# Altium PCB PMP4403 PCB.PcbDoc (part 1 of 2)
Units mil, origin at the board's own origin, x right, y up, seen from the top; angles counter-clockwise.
Board outline 2204 x 1635 mil, 2 copper layers (Top Layer, Bottom Layer), stack 62 mil thick; 78 components, 89 nets, 246 pads, 22 vias.
Unrouted connection lines stored in the file: 1.
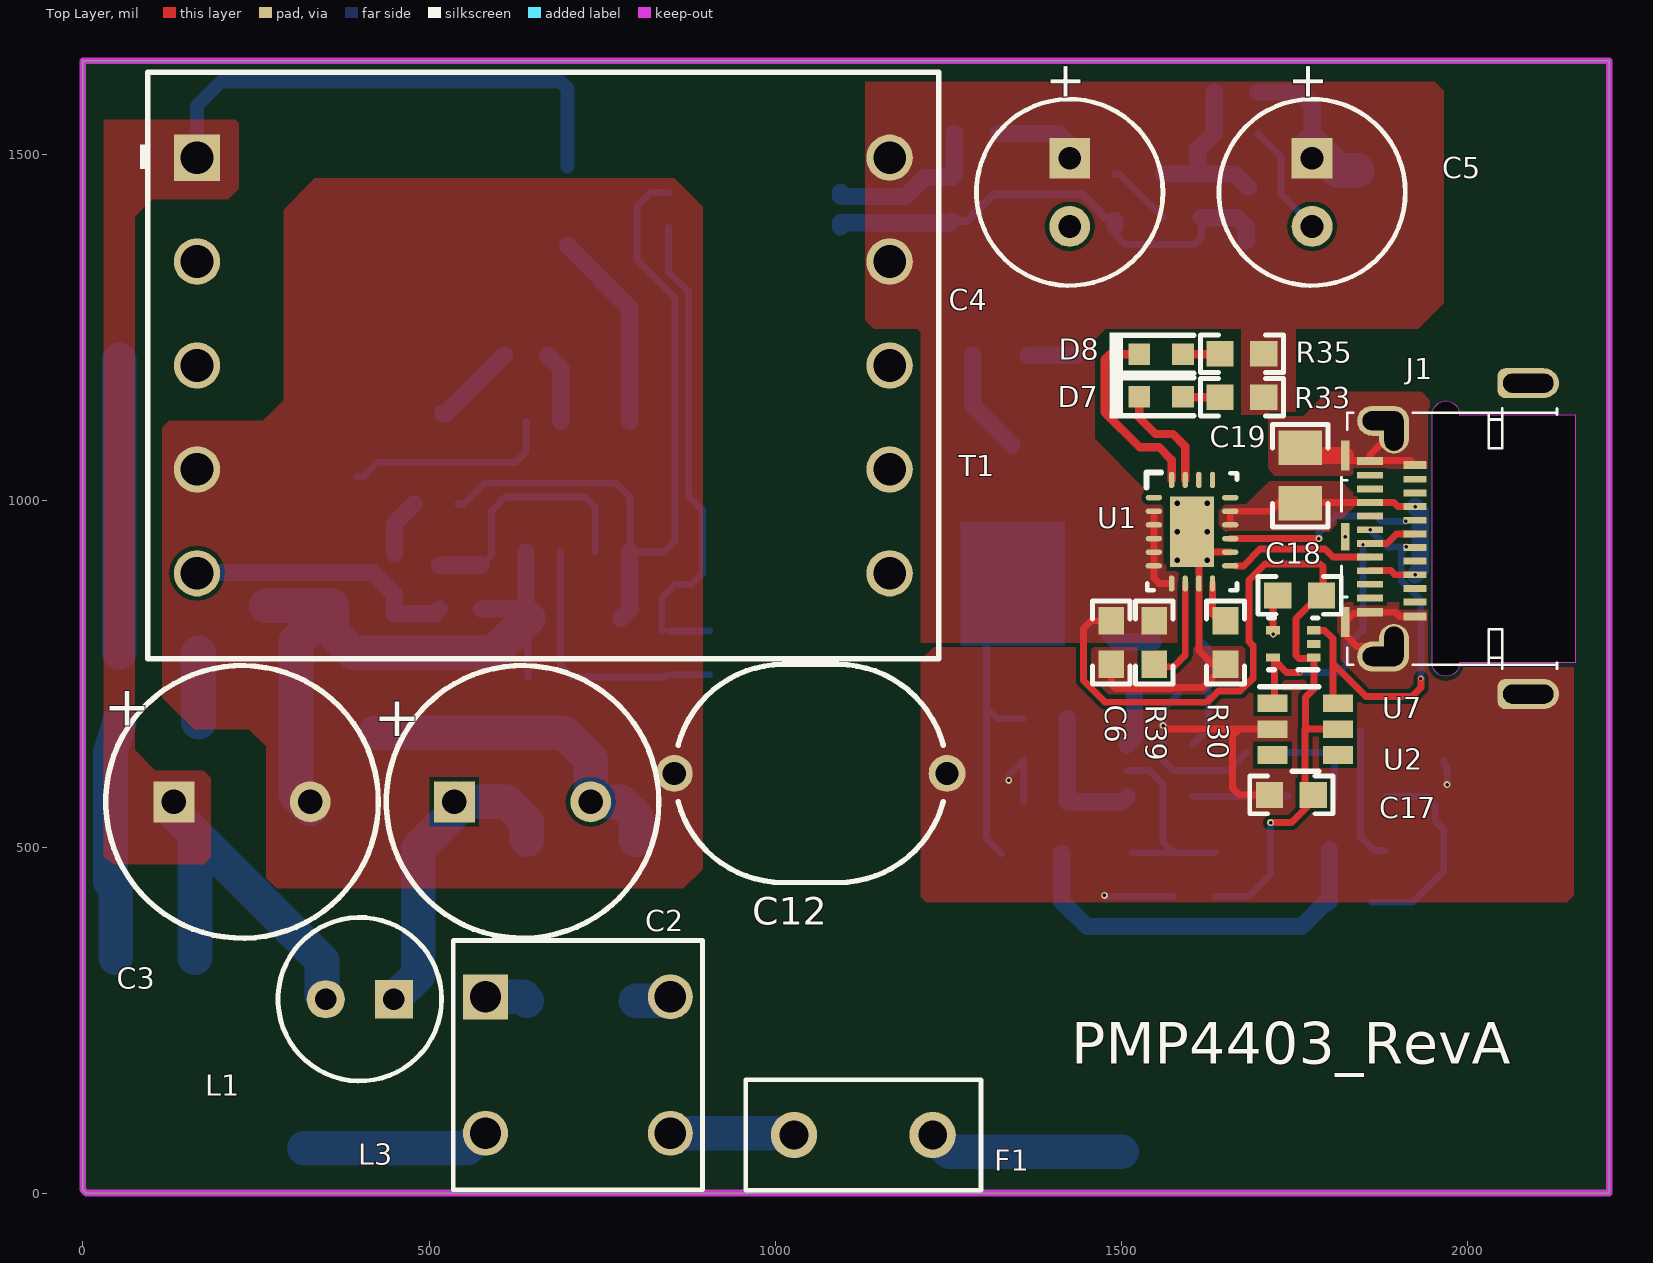
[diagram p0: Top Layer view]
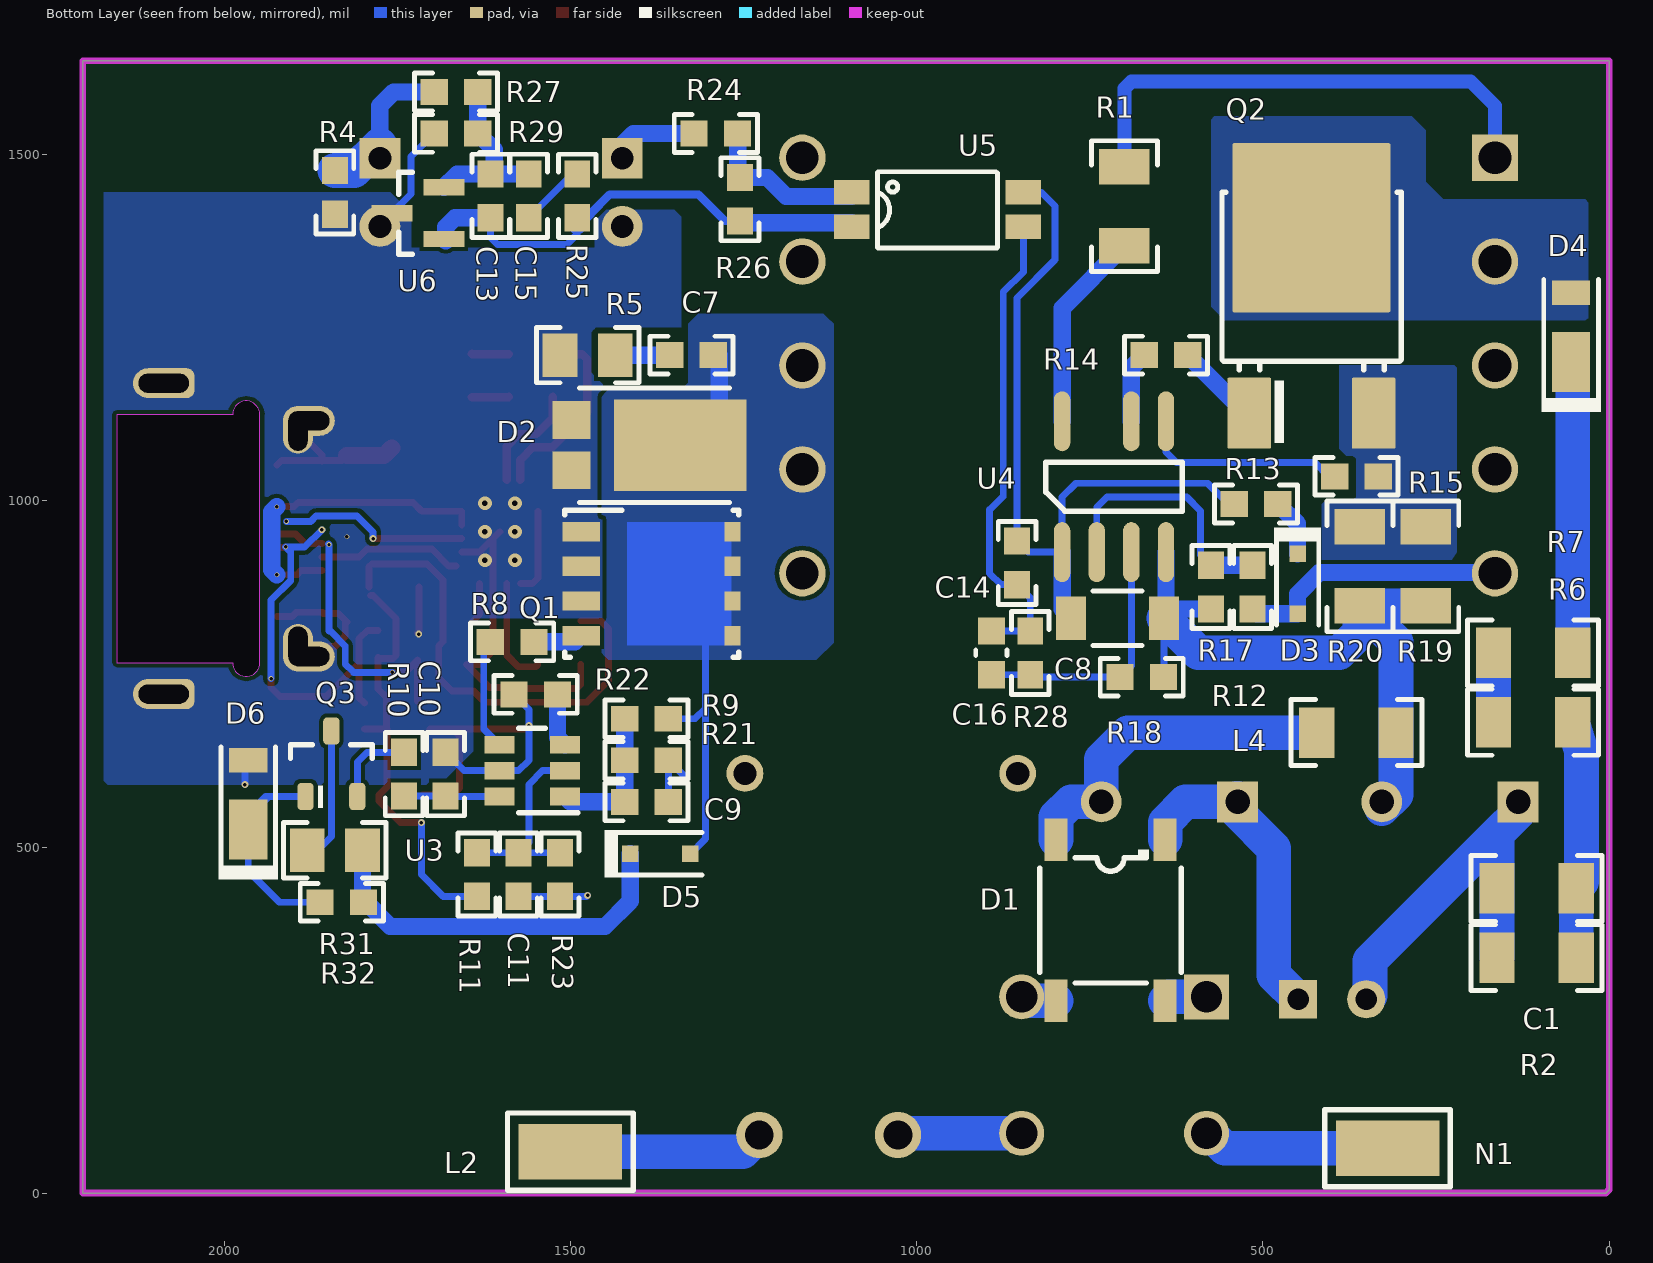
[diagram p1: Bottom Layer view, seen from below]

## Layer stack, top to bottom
Top Solder: solder mask 0.4, Solder Resist, Dk 3.5
Top Layer: signal copper 1.4
Dielectric1: core 59.2, FR-4, Dk 4.8
Bottom Layer: signal copper 1.4
Bottom Solder: solder mask 0.4, Solder Resist, Dk 3.5

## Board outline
5.02,0.42 0.02,5.42 0.02,1635.42 2204.02,1635.42 2204.02,0.42

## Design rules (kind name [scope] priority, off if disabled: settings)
AcuteAngle [All] p1: minimum=4.50000000000000E+0001 checktracksonly=FALSE
AssemblyTestPointUsage [All] p1: valid=2
Clearance Clearance_BoardEdge_MountingHoles [OnCopper and InComponentClass('Mounting Holes') vs IsKeepOut] p1: gap=40
Clearance Clearance_BoardEdge_Poly [OnCopper and InPoly vs IsKeepOut] p2: gap=25
Clearance Clearance_BoardEdge [OnCopper and Not InComponentClass('Logo') and not InComponentClass('FiducialMark') and not InRegion(1000,500,4000,800) and Not IsKeepout vs IsKeepOut] p3: gap=5
Clearance Clearance_Poly [InPolygon] p4: gap=6
Clearance [All] p5: gap=6
ComponentClearance ComponentClearance_Logo [All] p1: gap=10 collisioncheckmode=3 verticalgap=10 showdistances=TRUE
ComponentClearance ComponentClearance_ScrewToNut [(HasFootprint('NY PMS 440 0025 PH')) vs (HasFootprint('Keystone_1902C'))] p2: gap=5 collisioncheckmode=3 verticalgap=10 showdistances=FALSE
ComponentClearance ComponentClearance_MountingHoles [InComponentClass('Mounting Holes')] p3: gap=10 collisioncheckmode=3 verticalgap=100000 showdistances=FALSE
ComponentClearance ComponentClearance_SmallPassives [HasFootprint('0201*') or HasFootprint('0402*') or HasFootprint('0508') or HasFootprint('0603*') or HasFootprint('0612') or HasFootprint('0805*') or HasFootprint('0815*') or HasFootprint('0830*') or HasFootprint('1206*') or HasFootprint('1210*') or HasFootprint('1808*') or HasFootprint('1812*') or HasFootprint('1825*') or HasFootprint('2010*') or HasFootprint('2220*') or HasFootprint('2225*') or HasFootprint('2512*') or HasFootprint('2728*') or HasFootprint('3518*') vs HasFootprint('0201*') or HasFootprint('0402*') or HasFootprint('0508') or HasFootprint('0603*') or HasFootprint('0612') or HasFootprint('0805*') or HasFootprint('0815*') or HasFootprint('0830*') or HasFootprint('1206*') or HasFootprint('1210*') or HasFootprint('1808*') or HasFootprint('1812*') or HasFootprint('1825*') or HasFootprint('2010*') or HasFootprint('2220*') or HasFootprint('2225*') or HasFootprint('2512*') or HasFootprint('2728*') or HasFootprint('3518*')] p4: gap=10 collisioncheckmode=3 verticalgap=10 showdistances=FALSE
ComponentClearance ComponentClearance_THtoSMT [IsThruComponent vs IsSMTComponent] p5: gap=10 collisioncheckmode=3 verticalgap=100000 showdistances=FALSE
ComponentClearance ComponentClearance_THtoTH [IsThruComponent vs IsThruComponent] p6: gap=10 collisioncheckmode=3 verticalgap=100000 showdistances=FALSE
ComponentClearance [All] p7: gap=10 collisioncheckmode=3 verticalgap=10 showdistances=FALSE
DiffPairsRouting [All] p1: maxlimit=100 minlimit=10 mostfreqgap=10 toplayer_minwidth=15 toplayer_maxwidth=15 toplayer_prefwidth=15 bottomlayer_minwidth=15 bottomlayer_maxwidth=15 bottomlayer_prefwidth=15 maxuncoupledlength=1000
FabricationTestPointUsage TestPointUsage [All] p1: valid=2 allowmultiple=FALSE
FabricationTestpoint Testpoint [All] p1: side=3 testpointundercomponent=TRUE minsize=40 maxsize=100 preferedsize=60 minholesize=0 maxholesize=40 preferedholesize=32 testpointgrid=1 allowsidetop=TRUE allowsidebottom=TRUE usegrid=TRUE gridtolerance=0.01
FanoutControl Fanout_LCC [IsLCC] p1: bgadir=Out bgaviamode=Centered fanoutstyle=Auto fanoutdirection=Alternating viagrid=1 // Fanout_LCC (Default Rule)
FanoutControl Fanout_BGA [IsBGA] p2: bgadir=Out bgaviamode=Centered fanoutstyle=Auto fanoutdirection=Alternating viagrid=1 // Fanout_BGA (Default Rule)
FanoutControl Fanout_Default [All] p4: bgadir=Out bgaviamode=Centered fanoutstyle=Auto fanoutdirection=Alternating viagrid=1 // Fanout_Default (Default Rule)
FanoutControl Fanout_Small [(CompPinCount < 5)] p5: bgadir=Out bgaviamode=Centered fanoutstyle=Auto fanoutdirection=OutThenIn viagrid=1 // Fanout_Small (Default Rule)
HoleSize [All] p1: absolutevalues=TRUE maxlimit=251 minlimit=6 maxpercent=80.000 minpercent=20.000
MinimumAnnularRing [All] p1: minimumring=3
MinimumSolderMaskSliver MinimumSolderMaskSliver_Logo [InComponentClass('Logo') vs InComponentClass('Logo')] p1: minsoldermaskwidth=0.7
MinimumSolderMaskSliver [All] p2: minsoldermaskwidth=0
PlaneConnect [All] p1: planeconnectstyle=Direct reliefexpansion=10 reliefentries=4 reliefconductorwidth=10 reliefairgap=10
PolygonConnect [All] p1: connectstyle=Direct reliefconductorwidth=10 reliefentries=4 polygonreliefangle="90 Angle" airgapwidth=10
RoutingCorners [All] p1: cornerstyle=45-Degree minsetback=10 maxsetback=100
RoutingVias [All] p1: holewidth=16 width=34 viastyle="Through Hole" minholewidth=8 minwidth=16 maxholewidth=40 maxwidth=65
SMDToCorner [All] p1: distance=0
SilkToSilkClearance [All] p1: silktosilkclearance=0
SilkToSolderMaskClearance SilkscreenOverComponentPads [IsPad] p1: minsilkscreentomaskgap=0 clearancetoexposedcopper=TRUE
SolderMaskExpansion [All] p1: expansion=3
UnpouredPolygon [All] p1: allowunpoured=FALSE
Width [All] p1: maxlimit=100 minlimit=6 preferedwidth=10 checkconnectedcopper=TRUE
14 further rules are at their usual default settings.

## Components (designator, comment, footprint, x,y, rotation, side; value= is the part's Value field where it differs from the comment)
C1 "GRM31A5C2J331JW01D" 1206 105.02,440.42 r180 bottom
C2 "EEUED2G100" CAPPR5-10X20 635.02,565.42 r0 top
C3 "EEUED2G100" CAPPR5-10X20 230.02,565.42 r0 top
C4 "6SEPC470MW" SEPC_C9 1425.02,1445.42 r270 top
C5 "6SEPC470MW" SEPC_C9 1775.02,1445.42 r270 top
C6 "C1608X7R1E104K" 0603 1485.02,795.42 r270 top
C7 "06035A102KAT2A" 0603 1325.02,1210.42 r180 bottom
C8 "GMK316AB7106KL-TR" 1206_190 710.02,830.42 r180 bottom
C9 "06035A150JAT2A" 0603 1390.02,565.42 r180 bottom
C10 "GRM188R61E105KA12D" 0603 1680.02,605.42 r90 bottom
C11 "06035A150JAT2A" 0603 1575.02,460.42 r270 bottom
C12 "DE1B3KX101K" CAPRD1000W60D1000H1400 1051.02,606.42 r180 top
C13 "C0603X223K5RACTU" 0603 1615.02,1440.42 r270 bottom
C14 "C0603X223K5RACTU" 0603 855.02,910.42 r270 bottom
C15 "C0603X223K5RACTU" 0603 1560.02,1440.42 r270 bottom
C16 "C0603C105K3RACTU" 0603_095 892.02,780.42 r270 bottom
C17 "06033C104JAT2A" 0603 1745.02,575.42 r180 top
C18 "06033C104JAT2A" 0603 1757.02,863.42 r180 top
C19 "C0805C106K8PACTU" 0805_HV 1758.02,1036.42 r90 top
D1 "MDB6S" MICRODIP_4 720.02,394.42 r270 bottom
D2 "PDS1040L-13" PowerDI5 1420.02,1080.42 r180 bottom
D3 "BAS20HT1" sod-323 450.02,880.42 r270 bottom
D4 "DFLR1600-7" powerDI123 55.02,1250.42 r90 bottom
D5 "BAS20HT1" sod-323 1370.02,490.42 r180 bottom
D6 "DFLZ6V2-7" powerDI123 1965.02,575.42 r90 bottom
D7 "150060GS75000" WL-SMCW_GREEN 1557.02,1150.42 r0 top
D8 "150060GS75000" WL-SMCW_GREEN 1557.02,1211.69 r0 top
F1 "39213150000" FUSE_392 1127.02,84.42 r0 top
J1 "20-0000016-01" Lintes_20-0000016-01 2155.02,945.42 r90 top
L1 "7447462471" WE-TI_5075 400.02,280.42 r180 top
L2 "TESTPOINT" Keystone_5019 1500.02,60.42 r180 bottom
L3 "RLTI-1081" IND_RLTI-1081 715.02,185.42 r0 top
L4 "HZ1206E152R-10" 1206 365.02,665.42 r180 bottom
N1 "TESTPOINT" Keystone_5019 320.02,65.42 r0 bottom
Q1 "CSD18509Q5B" TRANS_NexFET_Q5B 1375.02,880.42 r180 bottom
Q2 "AOD7N65" DPAK 430.02,1260.42 r90 bottom
Q3 "MMBT3904" SOT-23 1845.02,620.42 r90 bottom
R1 "CRCW1206100KJNEA" 1206 700.02,1425.42 r90 bottom
R2 "CRCW1206330KJNEA" 1206 105.02,340.42 r0 bottom
R4 "CRCW0603100KJNEA" 0603 1840.02,1445.42 r90 bottom
R5 "CRCW080520R0JNEA" 0805_HV 1475.02,1210.42 r0 bottom
R6 "CRCW1206150RJNEA" 1206 110.02,680.42 r180 bottom
R7 "CRCW1206150RJNEA" 1206 110.02,780.42 r0 bottom
R8 "CRCW06032R00JNEA" 0603 1584.02,796.42 r0 bottom
R9 "CRCW0603150KFKEA" 0603 1390.02,685.42 r180 bottom
R10 "CRCW06032R00JNEA" 0603 1740.02,605.42 r90 bottom
R11 "CRCW060391K0JNEA" 0603 1635.02,460.42 r270 bottom
R12 "CRCW060368K0JNEA" 0603 515.02,875.42 r270 bottom
R13 "CRCW060322R0JNEA" 0603 510.02,995.42 r180 bottom
R14 "CRCW06030000Z0EA" 0603 640.02,1210.42 r180 bottom
R15 "CRCW06031K50JNEA" 0603 365.02,1035.42 r180 bottom
R17 "CRCW060339K0JNEA" 0603 575.02,875.42 r90 bottom
R18 "CRCW060320K0FKEA" 0603 675.02,745.42 r0 bottom
R19 "CRCW12061R00JNEA" 1206 265.02,905.42 r90 bottom
R20 "CRCW12062R00JNEA" 1206 360.02,905.42 r90 bottom
R21 "CRCW060310K0JNEA" 0603 1390.02,625.42 r0 bottom
R22 "CRCW060313K0JNEA" 0603 1550.02,720.42 r180 bottom
R23 "CRCW060347K0JNEA" 0603 1514.95,460.42 r90 bottom
R24 "CRCW06031K00FKEA" 0603 1290.02,1530.42 r0 bottom
R25 "CRCW060322K0JNEA" 0603 1490.02,1440.42 r90 bottom
R26 "CRCW06032K00FKEA" 0603 1255.02,1435.42 r90 bottom
R27 "CRCW060310K0FKEA" 0603 1665.02,1590.42 r0 bottom
R28 "CRCW0603100KFKEA" 0603 836.02,780.42 r90 bottom
R29 "CRCW060310K0FKEA" 0603 1665.02,1530.42 r180 bottom
R30 "CRCW0603100KFKEA" 0603 1650.02,795.42 r90 top
R31 "CRCW080522R0JNEA" 0805_HV 1840.02,495.42 r180 bottom
R32 "CRCW06031K00FKEA" 0603 1830.02,420.42 r180 bottom
R33 "CRCW060310K0JNEA" 0603 1673.67,1149.63 r0 top
R35 "CRCW060310K0JNEA" 0603 1673.67,1212.42 r0 top
R39 "CRCW060310K0JNEA" 0603 1547.07,795.42 r90 top
T1 "750342752" Wurth_750342752 665.02,1195.42 r0 top
U1 "TPS25810RVC" RVC0020A 1601.67,955.42 r0 top
U2 "TPS2514ADBV" DBV0006A_N 1765.02,670.42 r0 top
U3 "UCC24632" DBV0006A_N 1555.02,610.42 r0 bottom
U4 "UCC28740DR" D0007A_N 715.02,1020.42 r90 bottom
U5 "TCMT1107" SOP-4 970.02,1420.42 r180 bottom
U6 "TL431AIDBZR" DBZ0003A_N 1720.02,1415.42 r0 bottom
U7 "TPD2E001DRLRG4" DRL0005A 1748.02,793.42 r180 top

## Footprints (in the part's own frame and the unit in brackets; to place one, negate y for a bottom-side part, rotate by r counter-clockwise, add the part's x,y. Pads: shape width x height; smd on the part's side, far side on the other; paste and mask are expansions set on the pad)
0603 [mm] "0603 from SM-752 data"
  rect 1x0.95 smd: 1(-0.8,0) 2(0.8,0)
  silkscreen extent -1.52,-0.69 1.52,0.69, body extent -0.87,-0.47 0.87,0.47, height 0.85
0603_095 [mm] "0603_095"
  rect 1x1 smd: 1(-0.8,0) 2(0.8,0)
  silkscreen extent -0.1,-0.58 0.1,0.58, body extent -0.87,-0.48 0.87,0.48, height 0.95
0805_HV [mil] "0805 with 30mil clearance between pads"
  rect 50x63 smd: 1(-40,0) 2(40,0)
  silkscreen extent -74,-40 74,40, body extent -43,-29 43,29, height 43
1206 [mm] "1206 from SM-752 data"
  rect 1.3x1.85 smd: 1(-1.45,0) 2(1.45,0)
  silkscreen extent -2.4,-1.21 2.4,1.21, body extent -1.7,-0.9 1.7,0.9, height 1.35
1206_190 [mm] "1206_190"
  rect 1.1x1.6 smd: 1(-1.7,0) 2(1.7,0)
  silkscreen extent -0.9,-1 0.9,1, body extent -1.75,-0.95 1.75,0.95, height 1.9
CAPPR5-10X20 [mm] "Capacitor, Electrolytic, Radial; Body 10 x 20 mm (Dia.xH typ); Pin Spacing 5 mm (typ)"
  rect 1.5x1.5 hole 0.9: 1(-2.5,0)
  round 1.5 hole 0.9: 2(2.5,0)
  silkscreen extent -5,-5 5,5, body extent -5.01,-5.01 5.01,5.01, height 22
CAPRD1000W60D1000H1400 [mm] "Disk, Radial Capacitor"
  round 1.35 hole 0.85: 1(-5,0) 2(5,0)
  silkscreen extent -4.86,-4 4.86,4, body extent -5.67,-4 5.7,4, height 13.99
D0007A_N [mm] "SOIC, 7-Leads, Body 4.9x3.9mm, Pitch 1.27mm, IPC Medium Density"
  oval 2.2x0.6 smd: 1(-2.4,1.905) 2(-2.4,0.635) 3(-2.4,-0.635) 4(-2.4,-1.905) 5(2.4,-1.905) 6(2.4,-0.635) 8(2.4,1.905)
  silkscreen extent -0.9,-2.5 0.9,2.5, body extent -3,-2.5 3,2.5, height 1.54
DBV0006A_N [mm] "SOT23, 6-Leads, Body 2.9x1.6mm, Pitch 0.95mm, Lead Span 2.8mm, IPC Medium Density"
  rect 1.1x0.65 smd: 1(-1.2,0.95) 2(-1.2,0) 3(-1.2,-0.95) 4(1.2,-0.95) 5(1.2,0) 6(1.2,0.95)
  silkscreen extent -1.68,-1.55 0.5,1.55, body extent -1.42,-1.46 1.42,1.46, height 1.11
DBZ0003A_N [mm] "SOT23, 3-Leads, Body 2.9x1.3mm, Pitch 0.95mm, Lead Span 2.4mm, IPC Medium Density"
  rect 1.5x0.6 smd: 1(-0.95,0.95) 2(-0.95,-0.95) 3(0.95,0)
  silkscreen extent 0.2,-1.5 0.7,1.5, body extent -1.26,-1.46 1.26,1.46, height 0.96
DPAK [mm] "D-PAK, 3-Pads, Body 6.22x6.73mm (max), TO-252AA using nominal STEP model"
  rrect6% 2.6x1.6 smd: 1(-3.4,2.28) 3(-3.4,-2.28)
  rrect2% 6.2x5.8 smd paste-2.9: 4(3.4,0)
  silkscreen extent -4.5,-3.3 4.7,3.28, body extent -3.86,-3.29 5.84,3.29, height 2.48
DRL0005A [mm] "SOTFL, 5-Flat Leads, Body 1.2x1.6x0.6mm, Pitch 0.5mm, TI recommended"
  rect 0.5x0.3 smd: 1(-0.75,0.5) 2(-0.75,0) 3(-0.75,-0.5) 4(0.75,-0.5) 5(0.75,0.5)
  silkscreen extent -0.9,-0.95 0.9,0.95, body extent -0.85,-0.85 0.85,0.85, height 0.62
FUSE_392 [mm] "LITTELFUSE"
  round 1.7 hole 1.05: 1(-2.54,0) 2(2.54,0)
  silkscreen extent -4.32,-2.03 4.32,2.03, body extent -4.25,-2 4.25,2, height 8
IND_RLTI-1081 [mm] "Renco"
  rect 1.65x1.65 hole 1.15: 1(-3.391,2.502)
  round 1.65 hole 1.15: 2(-3.391,-2.502) 3(3.391,-2.502) 4(3.391,2.502)
  silkscreen extent -4.57,-4.57 4.57,4.57, body extent -4.57,-4.57 4.57,4.57, height 9.17
Keystone_5019 [mm] "Test Point, Miniature, SMT"
  rect 3.8x2.03 smd: 1(0,0)
  silkscreen extent -2.31,-1.42 2.31,1.42, body extent -1.91,-1.02 1.9,1.02, height 2.29
Lintes_20-0000016-01 [mm] "Connector, Receptacle, USB Type C, SMT"
  rect 1.1x0.3 smd: 1(3.05,8.44) 3(-3.05,8.44)
  rect 1x0.3 smd: 2(0.07,8.44)
  rect 0.3x0.95 smd: A1(-2.7,7.525) A12(2.85,7.525)
  rect 0.25x0.95 smd: A2(-2.175,7.525) A3(-1.675,7.525) A4(-1.175,7.525) A5(-0.675,7.525) A6(-0.175,7.525) A7(0.325,7.525) A8(0.825,7.525) A9(1.325,7.525) A10(1.825,7.525) A11(2.325,7.525)
  rect 0.3x0.85 smd: B1(2.7,5.875) B12(-2.85,5.875)
  rect 0.25x0.85 smd: B2(2.175,5.875) B3(1.675,5.875) B4(1.175,5.875) B5(0.675,5.875) B6(0.175,5.875) B7(-0.325,5.875) B8(-0.825,5.875) B9(-1.325,5.875) B10(-1.825,5.875) B11(-2.325,5.875)
  oval 1.1x1.9 hole 0.7 slot 1.5 at 90 deg: H1(4.323,7.05) H3(-4.323,7.05)
  oval 1.65x1.1 hole 0.7 slot 1.45 at 0 deg: H2(3.949,6.65) H4(-3.949,6.65)
  oval 1.1x1.7 hole 0.7 slot 1.3 at 90 deg: H5(5.7,1.45) H7(-5.7,1.45)
  rrect50% 1.1x1.7 hole 0.7 slot 1.3 at 90 deg: H6(5.7,2) H8(-5.7,2)
  Keep-Out Layer board cut-out: -4.55,0 -4.55,4.25 -4.767,4.3 -4.941,4.438 -5.037,4.639 -5.037,4.861 -4.941,5.062 -4.767,5.2 -4.55,5.25 -4.55,5.25 -4.55,5.25 4.55,5.25 4.55,5.25 4.767,5.2 4.941,5.062 5.037,4.861 5.037,4.639 4.941,4.438 4.767,4.3 4.55,4.25 4.55,4.25 4.55,0
  silkscreen extent -4.77,0.68 4.77,8.58, body extent -5.8,-1.56 5.8,8.59, height 2.44
MICRODIP_4 [mm] "FAIRCHILD"
  rect 1.55x0.85 smd: 1(-2.95,2) 2(-2.95,-2) 3(2.95,-2) 4(2.95,2)
  silkscreen extent -2.6,-2.6 2.3,2.6, body extent -3.4,-2.57 3.4,2.57, height 1.45
PowerDI5 [mm] "Diodes Inc recommended land pattern, ap02001.pdf rev 60"
  rect 1.4x1.39 smd: 1(-1.991,0.92) 2(-1.991,-0.92)
  rect 4.86x3.36 smd: 3(1.991,0)
  silkscreen extent -1.7,-2.1 3.8,2.1, body extent -2.27,-2.02 4.33,2.03, height 1.17
powerDI123 [mm] "Diodes Inc recommended land pattern, document number DS30628 Rev. 6-2"
  rect 2.2x1.4 smd: 1(-1.275,0)
  rect 0.9x1.4 smd: 2(1.275,0)
  silkscreen extent -3.1,-1.09 1.76,1.09, body extent -2.37,-0.96 1.53,0.97, height 1
RVC0020A [mm] "TI"
  oval 0.6x0.2 smd: 1(-1.4,1.25) 2(-1.4,0.75) 3(-1.4,0.25) 4(-1.4,-0.25) 5(-1.4,-0.75) 6(-1.4,-1.25) 11(1.4,-1.25) 12(1.4,-0.75) 13(1.4,-0.25) 14(1.4,0.25) 15(1.4,0.75) 16(1.4,1.25)
  oval 0.2x0.6 smd: 7(-0.75,-1.9) 8(-0.25,-1.9) 9(0.25,-1.9) 10(0.75,-1.9) 17(0.75,1.9) 18(0.25,1.9) 19(-0.25,1.9) 20(-0.75,1.9)
  rect 1.6x2.6 smd paste-1: 21(0,0)
  silkscreen extent -1.68,-2.15 1.65,2.18, body extent -1.55,-2.05 1.55,2.05, height 0.8
SEPC_C9 [mm] "PANASONIC"
  rect 1.5x1.5 hole 0.838: 1(-1.25,0)
  round 1.5 hole 0.838: 2(1.25,0)
  silkscreen extent -3.42,-3.42 3.42,3.42, body extent -3.41,-3.41 3.41,3.41, height 9.05
sod-323 [mm] "NXP recommended land pattern"
  rect 0.6x0.6 smd paste-0.05: 1(-1.1,0) 2(1.1,0)
  silkscreen extent -2.06,-0.86 1.53,0.86, body extent -1.3,-0.67 1.3,0.68, height 1.1
SOP-4 [mm] "Vishay Half Pitch Mini-Flat Package"
  rect 1.3x0.9 smd: 1(-3.15,0.635) 2(-3.15,-0.635) 3(3.15,-0.635) 4(3.15,0.635)
  silkscreen extent -2.2,-1.41 2.2,1.39, body extent -3.5,-1.4 3.5,1.4, height 2.12
SOT-23 [mm] "SOT23, 3-Leads, Body 2.9x1.3mm, Pitch 0.95mm, Lead Span 2.5mm, IPC Medium Density"
  rrect50% 1x0.6 smd: 1(-1.2,0.95) 2(-1.2,-0.95) 3(1.2,0)
  silkscreen extent -1.62,-1.5 0.7,1.5, body extent -1.16,-1.45 1.21,1.45, height 1
TRANS_NexFET_Q5B [mm] "TI recommended land pattern (nominal) November 2012"
  rect 1.372x0.71 smd paste-0.4: 1(-2.776,1.905) 2(-2.776,0.635) 3(-2.776,-0.635) 4(-2.776,-1.905)
  rect 0.59x0.71 smd paste-0.3: 5(2.776,-1.905) 6(2.776,-0.635) 7(2.776,0.635) 8(2.776,1.905)
  Top Layer region: -1.106,2.26 2.744,2.26 2.744,-2.26 -1.106,-2.26
  silkscreen extent -3.38,-2.7 3,2.7, body extent -3.23,-2.55 2.87,2.55, height 1.06
WE-TI_5075 [mm] "Wurth WE-TI 5075"
  rect 1.4x1.4 hole 0.787: 1(-1.25,0)
  round 1.4 hole 0.787: 2(1.25,0)
  silkscreen extent -3,-3 3,3, body extent -3.01,-3.01 3.01,3.01, height 8.5
WL-SMCW_GREEN [mm] "WURTH"
  rect 0.8x0.8 smd: 1(-0.8,0) 2(0.8,0)
  silkscreen extent -1.9,-0.8 1.2,0.8, body extent -0.85,-0.45 0.85,0.45, height 0.8
Wurth_750342752 [mm] "TH, 10-Leads, Body 29x21.5mm, Pitch 3,81mm"
  rect 1.7x1.7 hole 1.2: 1(-12.7,7.62)
  round 1.7 hole 1.2: 2(-12.7,3.81) 3(-12.7,0) 4(-12.7,-3.81) 5(-12.7,-7.62) 6(12.7,-7.62) 7(12.7,-3.81) 8(12.7,0) 9(12.7,3.81) 10(12.7,7.62)
  silkscreen extent -14.8,-10.75 14.5,10.75, body extent -14.5,-10.75 14.5,10.75, height 12.01

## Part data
C1: "CAP, CERM, 330 pF, 630 V, +/- 5%, C0G/NP0, 1206"
C2 C3: "CAP, AL, 10 μF, 400 V, +/- 20%, 2.864788 ohm, TH"
C4 C5: "CAP, AL, 470 μF, 6.3 V, +/- 20%, 0.007 ohm, TH"
C6: "CAP, CERM, 0.1 μF, 25 V, +/- 10%, X7R, 0603"
C7: "CAP, CERM, 1000 pF, 50 V, +/- 10%, C0G/NP0, 0603"
C8: "CAP, CERM, 10 μF, 35 V, +/- 10%, X7R, 1206_190"
C9 C11: "CAP, CERM, 15 pF, 50 V, +/- 5%, C0G/NP0, 0603"
C10: "CAP, CERM, 1 μF, 25 V, +/- 10%, X5R, 0603"
C12: library part DE1E3KX222MA5BA01, "CAP, CERM, 100 pF, 250 V, +/- 20%, E, Disc 10x8mm"
C13 C14 C15: "CAP, CERM, 0.022 μF, 50 V, +/- 10%, X7R, 0603"
C16: "CAP, CERM, 1 μF, 25 V, +/- 10%, X7R, 0603_095"
C17 C18: "CAP, CERM, 0.1 μF, 25 V, +/- 5%, X7R, 0603"
C19: "CAP, CERM, 10 μF, 10 V, +/- 10%, X5R, 0805"
D1: "Diode, Switching-Bridge, 600 V, 1 A, Diode Bridge,6.5x1.3x5.0mm, SMT"
D2: "Diode, Schottky, 40 V, 10 A, PowerDI5"
D3 D5: library part BAV20WS-TP, "Diode, P-N, 150 V, 0.2 A, SOD-323"
D4: "Diode, Standard Recovery Rectifier, 600 V, 1 A, PowerDI123"
D6: "Diode, Zener, 6.2 V, 1 W, PowerDI123"
D7 D8: "LED, Green, SMD"
F1: "Fuse, 3.15 A, 250 V, TH"
J1: "Connector, Receptacle, USB Type C, R/A, SMT"
L1: "Inductor, Unshielded Drum Core, Ferrite, 470 μH, 0.35 A, 1.58 ohm, TH"
L2 N1: library part 5019, "Test Point, Miniature, SMT"
L3: "Coupled inductor, 806 μH,  A, 0.27 ohm, +/- 25%, TH"
L4: "Ferrite Bead, 950 ohm @ 100 MHz, 0.5 A, 1206"
Q1: "MOSFET, N-CH, 40 V, 38 A, SON 5x6mm"
Q2: "MOSFET, N-CH, 650 V, 7 A, DPAK"
Q3: library part "MMBT3904, Fairchild Semiconductor", "Transistor, NPN, 40 V, 0.2 A, SOT-23"
R1: "RES, 100 k, 5%, 0.25 W, 1206"
R2: "RES, 330 k, 5%, 0.25 W, 1206"
R4: "RES, 100 k, 5%, 0.1 W, 0603"
R5: "RES, 20, 5%, 0.125 W, 0805"
R6 R7: "RES, 150, 5%, 0.25 W, 1206"
R8 R10: "RES, 2.0, 5%, 0.1 W, 0603"
R9: "RES, 150 k, 1%, 0.1 W, 0603"
R11: "RES, 91 k, 5%, 0.1 W, 0603"
R12: "RES, 68 k, 5%, 0.1 W, 0603"
R13: "RES, 22, 5%, 0.1 W, 0603"
R14: "RES, 0, 5%, 0.1 W, 0603"
R15: "RES, 1.5 k, 5%, 0.1 W, 0603"
R17: "RES, 39 k, 5%, 0.1 W, 0603"
R18: "RES, 20.0 k, 1%, 0.1 W, 0603"
R19: "RES, 1.0, 5%, 0.25 W, 1206"
R20: "RES, 2.0, 5%, 0.25 W, 1206"
R21 R33 R35 R39: "RES, 10 k, 5%, 0.1 W, 0603"
R22: "RES, 13 k, 5%, 0.1 W, 0603"
R23: "RES, 47 k, 5%, 0.1 W, 0603"
R24 R32: "RES, 1.00 k, 1%, 0.1 W, 0603"
R25: "RES, 22 k, 5%, 0.1 W, 0603"
R26: "RES, 2.00 k, 1%, 0.1 W, 0603"
R27 R29: "RES, 10.0 k, 1%, 0.1 W, 0603"
R28 R30: "RES, 100 k, 1%, 0.1 W, 0603"
R31: "RES, 22, 5%, 0.125 W, 0805"
T1: "Transformer, 515 uH, TH"
U1: "USB Type-C DFP Controller and Power Switch with Load Detection, RVC0020A"
U2: "USB Dedicated Charging Port Controller, DBV0006A"
U3: library part UCC24630DBV, "SYNCRONOUS RECTIFIER CONTROLLER WITH LOW POWER STANDBY, DBV0006A"
U4: "Constant-Voltage, Constant-Current Flyback Controller Using Opto-Coupler Feedback, D0007A"
U5: "Optocoupler, 3.75 kV, 80-160% CTR, SMD-4"
U6: "Adjustable Precision Shunt Regulator, 34 ppm / degC, 100 mA, -40 to 85 degC, 3-pin SOT-23 (DBZ), Green (RoHS & no Sb/Br)"
U7: "Low-Capacitance + / - 15 kV ESD-Protection Array for High-Speed Data Interfaces, 2 Channels, -40 to +85 degC, 5-pin SOT (DRL), Green (RoHS & no Sb/Br)"

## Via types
v1: diameter 10, hole 5, Top Layer to Bottom Layer, 8 vias
v2: diameter 7, hole 5, Top Layer to Bottom Layer, 8 vias
v3: diameter 19.68, hole 7.87, Top Layer to Bottom Layer, 6 vias

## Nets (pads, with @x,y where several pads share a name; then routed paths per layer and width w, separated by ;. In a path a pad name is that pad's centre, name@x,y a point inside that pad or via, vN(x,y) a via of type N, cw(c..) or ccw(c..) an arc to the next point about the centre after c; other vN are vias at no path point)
$$$1: 
$$$980: 
$$$2093: 
$$$2515: 
$$$4302: 
$$$4615: 
$$$5424: 
$$$6648: 
$$$6732: 
$$$7639: 
$$$11187: 
$$$14440: 
$$$15027: 
$$$15511: 
$$$15883: 
$$$15885: 
$$$15918: 
$$$15978: 
$$$15988: 
$$$15990: 
$$$16008: 
$$$16010: 
$$$16065: 
$$$16085: 
$$$18434: 
$$$19469: 
$$$20004: 
$$$21110: 
$$$24763: 
$$$26288: 
$$$27032: 
$$$29416: 
$$$30096: 
$$$30409: 
$$$31676: 
GND: C3.2 C4.2 C5.2 C6.2 C8.2 C9.2 C10.2 C11.2 C12.1 C12.2 C17.2 C18.2 C19.2 D2.1 D2.2 D6.2 J1.1 J1.2 J1.3 J1.A1 J1.A12 J1.B1 J1.B12 J1.H1 J1.H2 J1.H3 J1.H4 J1.H5 J1.H6 J1.H7 J1.H8 L4.2 Q1.1 Q1.2 Q1.3 R4.1 R5.2 R17.1 R18.1 R19.1 R20.1 R21.1 R22.1 R23.1 R29.1 R30.1 T1.4 U1.9 U1.12 U1.21 U2.2 U3.5 U4.4 U6.3 U7.4 | length 2996.5
  Top Layer w10: C6.2@1485.02,763.93 1485.02,735.42 1491.2,729.24 1571.98,729.24 1573.16,730.42 1616.51,730.42 R30.1@1650.02,763.93 1631.51,763.93 1611.51,783.93 U1.9@1611.51,880.62 U1.21@1611.51,945.58 ; v1(1560.02,675.42) 1565.02,670.42 1670.02,670.42 ; U1.21@1601.67,955.42 U1.21@1611.51,945.58 ; U1.12@1656.79,925.89 1631.2,925.89 U1.21@1611.51,945.58 ; U2.2@1702.77,670.42 1670.02,670.42 ; C17.2@1713.52,575.42 1670.02,575.42 1660.02,585.42 1660.02,660.42 1670.02,670.42 ; C18.2@1718.52,875.42 1718.52,811.18 1720.49,809.21 v1(1718.86,807.58) ; 1829.81,1058.42 J1.A12@1858.76,1058.42 ; J1.A12@1858.76,1057.63 J1.A12@1858.76,1058.42 ; J1.H2@1893.2,1100.89 1858.76,1066.45 J1.A12@1858.76,1058.42 ; J1.H4@1909.7,773.45 J1.H4@1893.2,789.95 1840.02,789.95 1825.02,804.95 1825.02,825.34 J1.3@1822.73,825.34 1835.02,837.63 1857.26,837.63 J1.A1@1858.76,839.12 1895.61,839.12 1901.52,833.22 J1.B12@1923.72,833.22 ; J1.B1@1923.72,1051.72 1917.02,1058.42 J1.A12@1858.76,1058.42
  Top Layer w25: C19.2@1758.02,1076.42 1768.94,1065.5 J1.1@1822.73,1065.5
  Bottom Layer w10: C8.2@643.09,830.42 643.09,745.85 R18.1@643.52,745.42 ; v1(1337.02,596.42) 1337.02,603.92 R21.1@1358.52,625.42 C9.2@1358.52,565.42 ; v1(1475.02,430.42) 1476.51,428.93 R23.1@1514.95,428.93 C11.2@1575.02,428.93 ; R22.1@1581.51,720.42 1560.02,698.93 v1(1560.02,675.42) 1560.02,625.42 1575.02,610.42 U3.5@1602.26,610.42 1653.52,610.42 C10.2@1680.02,636.92 ; R29.1@1696.51,1530.42 1730.02,1496.92 1730.02,1442.82 U6.3@1757.42,1415.42 1757.42,1394.12 1775.02,1376.52 C5.2@1765.41,1376.52 ; D6.2@1965.02,625.62 1965.02,620.42 1970.02,615.42 v1(1970.02,590.42)
  Bottom Layer w25: R17.1@575.02,843.93 629.58,843.93 C8.2@640.02,833.49 ; U4.4@640.02,925.93 C8.2@640.02,833.49 ; C8.2@643.09,830.42 C8.2@640.02,833.49
  Bottom Layer w50: R19.1@265.02,848.33 R20.1@360.02,848.33 ; C3.2@328.44,555.42 307.93,575.93 L4.2@307.93,665.42 307.93,796.25 R20.1@360.02,848.33 ; C8.2@643.09,830.42 593.09,780.42 390.02,780.42 360.02,810.42 R20.1@360.02,848.33
  other v2: 1822.73,948.18
  other v3: 1580.02,914.08 1623.32,914.08 1580.02,955.42 1623.32,955.42 1580.02,996.76 1623.32,996.76
NET00062: 
NetC1_1: C1.1 C3.1 L1.2 R1.2 R2.2 T1.1 | length 1286.1
  Bottom Layer w20: T1.1@165.02,1495.42 165.02,1570.42 200.02,1605.42 690.02,1605.42 700.02,1595.42 R1.2@700.02,1482.51
  Bottom Layer w50: C3.1@131.59,555.42 131.59,549.63 162.1,519.12 ; R2.2@162.1,340.42 C1.1@162.1,440.42 162.1,519.12 ; L1.2@350.8,280.42 345.41,285.82 345.41,335.82 162.1,519.12
NetC1_2: C1.2 R2.1 R6.2 | length 345.2
  Bottom Layer w50: R2.1@47.93,340.42 C1.2@47.93,440.42 47.93,442.51 40.02,450.42 40.02,637.51 R6.2@52.93,680.42
NetC2_1: C2.1 D1.1 L1.1 | length 456.5
  Bottom Layer w50: L1.1@449.23,280.42 484.23,315.42 484.23,498.06 C2.1@536.59,550.42 ; C2.1@536.59,565.42 C2.1@542.42,565.42 ; C2.1@536.59,570.42 537.42,570.42 C2.1@542.42,565.42 ; D1.1@641.28,510.56 641.28,536.16 612.02,565.42 C2.1@542.42,565.42
NetC2_2: C2.2 D1.2 L4.1 | length 496.3
  Bottom Layer w50: L4.1@422.1,665.42 695.02,665.42 733.44,627 C2.2@733.44,565.42 777.02,565.42 798.76,543.68 D1.2@798.76,510.56
NetC4_1: C4.1 C5.1 C6.1 C17.1 C18.1 R4.2 R11.2 R24.2 R27.2 R33.2 R35.2 R39.2 T1.9 T1.10 U1.2 U1.3 U1.4 U1.5 U1.6 U1.7 U2.5 U7.1 | length 1770.2
  Top Layer w10: C6.1@1485.02,826.92 1456.51,826.92 1445.02,815.42 1445.02,740.42 1476.2,709.24 1623.62,709.24 1639.8,725.42 1671.11,725.42 1690.02,744.33 1690.02,790.42 1683.84,796.6 1683.84,885.96 1707,909.12 1786.32,909.12 1790.51,904.93 C18.1@1790.51,875.42 ; 1546.32,888.65 1546.55,888.89 ; U1.2@1546.55,984.95 U1.3@1546.55,965.26 U1.4@1546.55,945.58 U1.5@1546.55,925.89 U1.6@1546.55,906.21 1546.55,888.89 ; 1555.17,880.26 1554.82,880.62 ; U1.7@1572.14,880.62 1554.82,880.62 ; v1(1715.02,535.42) 1745.02,535.42 1776.51,566.92 C17.1@1776.51,575.42 1765.02,586.92 1765.02,670.42 ; U7.1@1777.54,773.74 U7.1@1777.54,772.52 ; C18.1@1788.51,863.42 1785.12,863.42 1751.51,829.81 1751.51,776.95 1755.95,772.52 U7.1@1777.54,772.52 ; U2.5@1797.26,670.42 1765.02,670.42 ; 1546.55,888.89 1554.82,880.62 ; 1765.02,670.42 1765.33,670.74 1765.33,716.42 1777.54,728.63 U7.1@1777.54,772.52
  Bottom Layer w10: C4.1@1422.52,1511.82 C4.1@1425.02,1509.32 ; R11.2@1635.02,428.93 1683.52,428.93 1715.02,460.42 v1(1715.02,535.42)
  Bottom Layer w25: R24.2@1321.51,1530.42 1408.91,1530.42 C4.1@1425.02,1514.32 ; R27.2@1696.51,1590.42 1755.02,1590.42 1775.02,1570.42 C5.1@1775.02,1514.32
  Bottom Layer w50: C5.1@1775.02,1514.32 1812.42,1476.92 R4.2@1840.02,1476.92
NetC7_1: C7.1 R5.1 | length 70
  Bottom Layer w25: C7.1@1365.02,1210.42 R5.1@1435.02,1210.42
NetC7_2: C7.2 D2.3 D5.2 Q1.5 Q1.6 Q1.7 Q1.8 R9.2 T1.7 T1.8 | length 577.2
  Bottom Layer w10: 1305.02,845.42 1305.02,700.42 ; D5.2@1326.71,490.42 1305.02,512.11 1305.02,700.42 ; R9.2@1358.52,685.42 1320.02,685.42 1305.02,700.42
  Bottom Layer w25: C7.2@1285.02,1210.42 1285.02,1137.04 D2.3@1341.63,1080.42
NetC8_1: C8.1 C14.1 R13.1 U4.1 U5.4 | length 1081.8
  Bottom Layer w10: R13.1@541.51,995.42 550.02,995.42 580.02,1025.42 770.02,1025.42 790.02,1005.42 U4.1@790.02,925.93 839.03,925.93 C14.1@855.02,941.92 855.02,1293.12 800.02,1348.12 800.02,1425.42 820.02,1445.42 U5.4@846,1445.42
  Bottom Layer w25: C8.1@776.95,830.42 790.02,843.49 U4.1@790.02,925.93
NetC9_1: C9.1 R9.1 R21.2 U3.1 | length 269.4
  Bottom Layer w25: R21.2@1421.51,625.42 R9.1@1421.51,685.42 C9.1@1421.51,565.42 1500.17,565.42 U3.1@1507.77,573.02
NetC10_1: C10.1 R10.1 U3.6 | length 138.1
  Bottom Layer w10: U3.6@1602.26,573.02 1679.11,573.02 C10.1@1680.02,573.93 R10.1@1740.02,573.93
NetC11_1: C11.1 R11.1 R23.2 U3.2 | length 285.3
  Bottom Layer w10: U3.2@1507.77,610.42 1540.02,610.42 1560.02,590.42 1560.02,506.92 C11.1@1575.02,491.92 ; R23.2@1514.95,491.92 C11.1@1575.02,491.92 ; R11.1@1635.02,491.92 C11.1@1575.02,491.92
NetC13_1: C13.1 C15.1 R27.1 R29.2 U6.2 | length 260.8
  Bottom Layer w25: C15.1@1560.02,1471.92 C13.1@1615.02,1471.92 ; R27.1@1633.52,1590.42 R29.2@1633.52,1530.42 1610.02,1506.92 1610.02,1476.92 C13.1@1615.02,1471.92 ; U6.2@1682.61,1452.82 1663.52,1471.92 C13.1@1615.02,1471.92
